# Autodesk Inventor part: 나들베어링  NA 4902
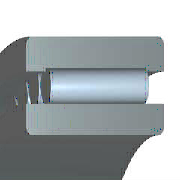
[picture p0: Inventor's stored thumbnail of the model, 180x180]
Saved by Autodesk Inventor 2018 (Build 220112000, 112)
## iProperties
Created: 2012-02
Part Number: 나들베어링  NA 4902
Material: 강철, 연강
Description: 니들 롤러 베어링
Document SubType Name: Modeling
Standard: JIS B 1536
Designer: mdu-01
Standards Organization: JIS
Language: ko-KR
Size Designation: NA 4902 15x28x13
Categories: <MemberInstance><Categories><Category DisplayName="샤프트 부품" InternalName="7f7aeb1f-a693-4053-b835-cee3144e0d98" Mnemonic="SHFT"><Category DisplayName="베어링" Inter
Density: 1 g/cm^3
Appearance: 강철(1)
IsCustomPart: 1
Author: mdu-01
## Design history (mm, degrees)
sketch "스케치"
  geometry: L1 (1.857, 11.5)-(11.143, 11.5); L2 (11.143, 11.5)-(11.143, 10); L3 (13, 10)-(0, 10); L4 (1.857, 10)-(1.857, 11.5); L5 (1.857, 10.75)-(11.143, 10.75); L6 (6.5, 10.75)-(6.5, 10); L7 (0, 7.5)-(13, 7.5); L8 (0, 14)-(13, 14); L9 (13, 7.5)-(13, 10); L10 (13, 11.35)-(13, 14); L11 (1.857, 11.35)-(0, 11.35); L12 (11.143, 11.35)-(13, 11.35); L13 (-6, 0)-(36, 0) reference; L14 (0, -1.9)-(0, 14.9) reference
  constraints: 24 end point, 8 point on line, 3 midpoint, 3 parallel, 3 perpendicular, 2 symmetric about line, 1 horizontal, 1 other
  dimensions: "d6" = 15 diameter of L7 L13 (= WD); "d7" = 20 diameter of L3 L13 (= KID1); "d8" = 28 diameter of L8 L13 (= BD); "d9" = 21.5 diameter of L6.start L13 (= 0.5 x WD + 0.5 x BD); "d10" = 22.7 diameter of L12 L13 (= 0.9 x BD + 0.9 x WD - 0.8 x KID1); "d11" = 23 diameter of L1 L13 (= BD + WD - KID1); "d12" = 1.85714 distance between parallel lines of L14 L4 (= 0.142857 x KB); "d13" = 13 distance between parallel lines of L14 L9 (= KB); "d14" = 11.14286 distance between parallel lines of L14 L2 (= 0.857143 x KB)
revolve "본체" stored, may be unused: angle "d17" = 90 deg
revolve "롤러" stored, may be unused: angle "d18" = 90 deg
body "Solid1"
fillet "모깎기1" dims "d0" = 0.3 (= KRS)
pattern_circular "IDS_ARRAYROLLER[SIMPL:T]" dims angle "d2" = 360 deg
other parameters: "WD" = 15 [user parameter; used in 6 equation terms], "BD" = 28 [user parameter; used in 6 equation terms], "KB" = 13 [user parameter; used in 3 equation terms], "KID1" = 20 [user parameter; used in 4 equation terms], "KRS" = 0.3 [user parameter; used in 1 equation term], "d3" = 0, "d4" = 0, "d5" = 0, "d15" = 0, "d16" = 0, "BC0" = 1.37e+07 [user parameter], "WR" = 7.5 (= 0.5 x WD) [user parameter], "BBA" = 0 [user parameter], "BC" = 1.02e+07 [user parameter], "BR" = 14 (= 0.5 x BD) [user parameter]
